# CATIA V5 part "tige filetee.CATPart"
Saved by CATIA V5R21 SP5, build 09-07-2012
Part number: tige filetee
Bounding box of the stored display mesh (mm): x -60 to 60, y -58.496 to 58.496, z 0 to 1700
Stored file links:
  \\etu.ad.univ-lorraine.fr\bordron1\Documents\Parts EPR\tige filetee.CATPart
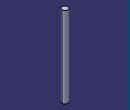
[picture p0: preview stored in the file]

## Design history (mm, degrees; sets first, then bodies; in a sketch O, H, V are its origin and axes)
AxisSystem1: origin (0, 0, 0), X (1, 0, 0), Y (0, 1, 0), Z (0, 0, 1)
Body1 (main body)
  Sketch1 on XY plane of AxisSystem1, origin (0, 0, 0), H (1, 0, 0), V (0, 1, 0)
    circle A1 centre (0, 0) radius 60
    radius A1 = 60
  Pad1: profile Sketch1, direction (0, 0, 1), length 1700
